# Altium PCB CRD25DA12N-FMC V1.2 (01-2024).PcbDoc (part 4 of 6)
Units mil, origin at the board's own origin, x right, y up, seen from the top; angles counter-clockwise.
Board outline 8000 x 8000 mil, 6 copper layers (Top Layer, Layer 2, Layer 3, Layer 4, Layer 5, Bottom Layer), stack 91 mil thick; 574 components, 325 nets, 1631 pads, 633 vias.
Unrouted connection lines stored in the file: 1.
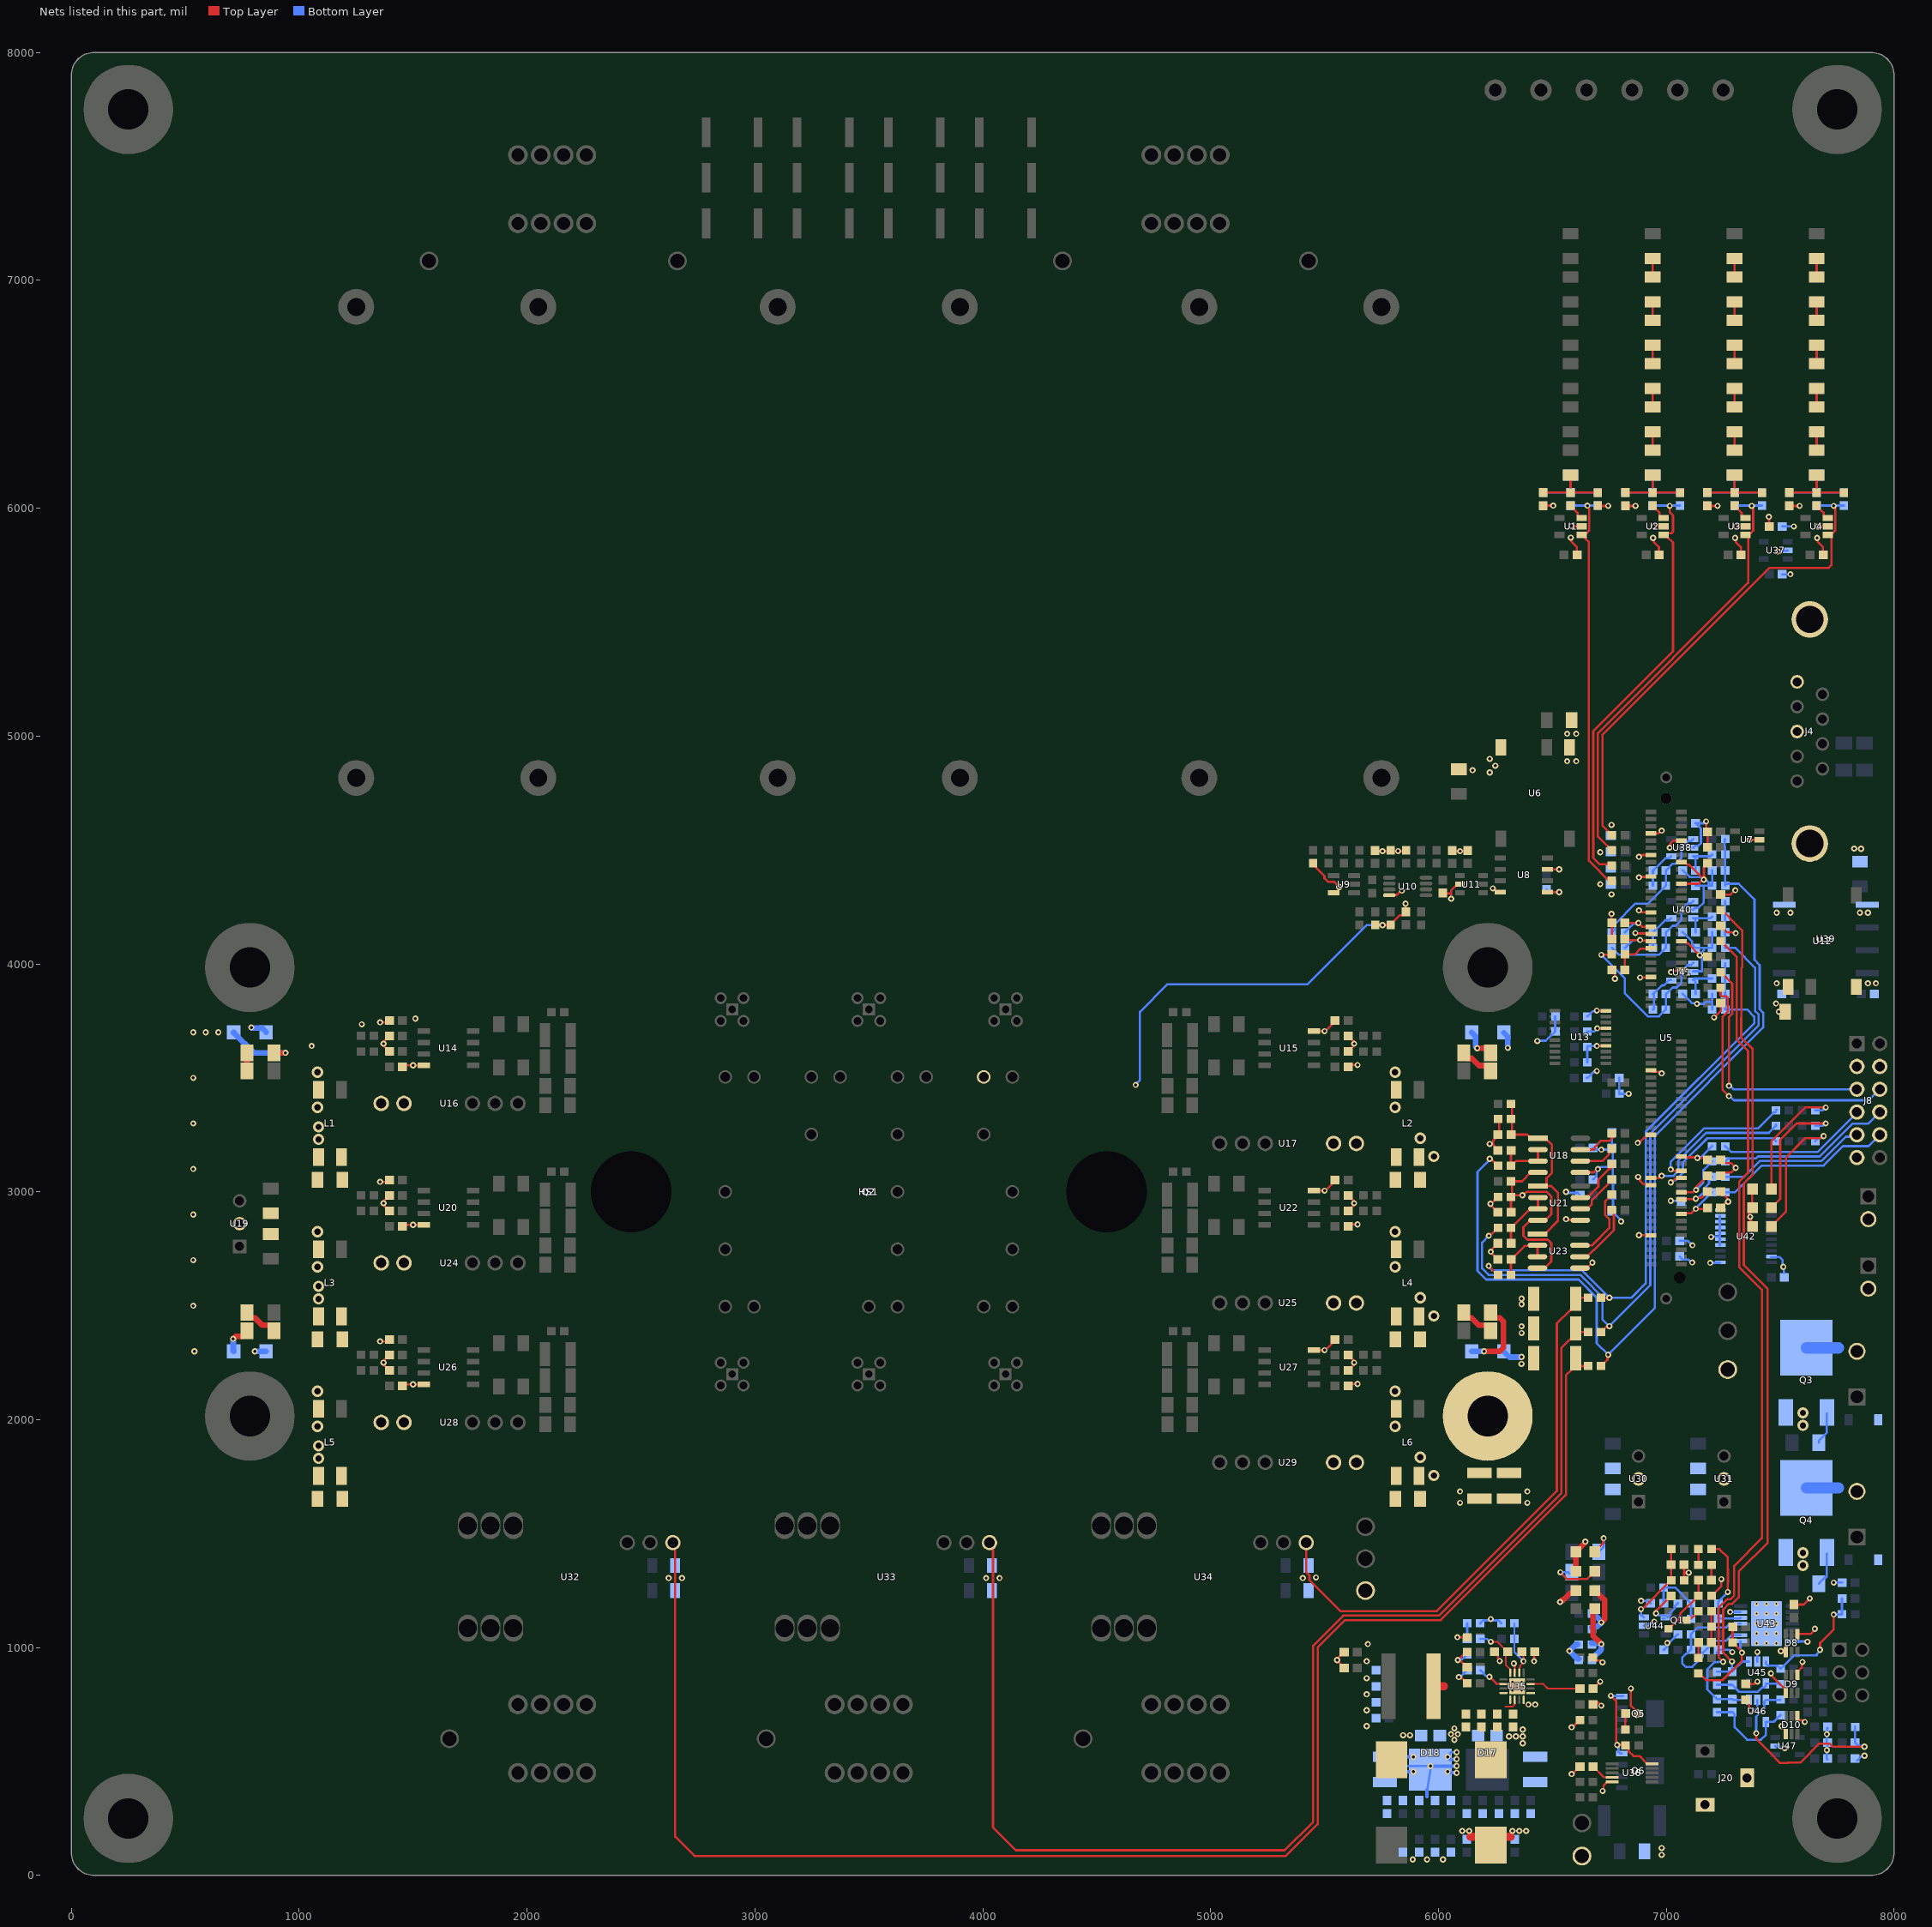
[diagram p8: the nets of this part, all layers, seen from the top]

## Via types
v1: diameter 27, hole 13, Top Layer to Bottom Layer, tented both sides, 537 vias
v2: diameter 50, hole 28, Top Layer to Bottom Layer, tented both sides, 76 vias
v3: diameter 19.68, hole 7.87, Top Layer to Bottom Layer, tented top, 15 vias
v4: diameter 19.68, hole 7.87, Top Layer to Bottom Layer, tented both sides, 5 vias

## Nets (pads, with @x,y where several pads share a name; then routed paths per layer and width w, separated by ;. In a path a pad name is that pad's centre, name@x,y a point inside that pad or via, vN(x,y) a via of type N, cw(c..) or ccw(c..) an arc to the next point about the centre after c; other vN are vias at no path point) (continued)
GND: C1.2 C2.2 C3.2 C4.2 C5.2 C6.2 C7.2 C8.2 C9.2 C10.2 C12.2 C13.2 C17.2 C19.2 C21.2 C22.2 C23.2 C24.2 C25.2 C26.2 C27.2 C28.2 C29.2 C32.2 C33.2 C34.2 C35.2 C38.2 C39.2 C44.2 C45.2 C46.2 C47.2 C50.2 C51.2 C54.2 C55.2 C56.2 C57.2 C58.2 C59.2 C60.2 C61.2 C64.2 C65.2 C66.2 C69.2 C70.2 C75.2 C76.2 C79.2 C80.2 C81.2 C82.2 C85.2 C86.2 C93.2 C96.2 C99.2 C100.2 C101.2 C102.2 C104.2 C105.2 C106.2 C107.2 C108.2 C113.2 C121.2 C122.2 C123.2 C124.2 C125.2 C127.2 C128.2 C129.2 C131.2 C132.2 C133.2 C134.2 C135.2 C137.2 C139.2 C140.2 C141.2 C143.2 C144.2 C145.2 C146.2 C147.2 C148.2 C149.2 C150.2 C151.2 C152.2 C153.2 C154.2 C155.2 C156.2 C157.2 C158.2 C159.2 C160.2 C161.2 C162.2 C163.2 C164.2 C165.2 C166.1 C167.1 C168.1 C170.2 C173.2 C174.2 C175.2 C176.2 C179.2 C182.2 C183.2 C184.2 C186.2 C187.2 C188.2 C190.2 C191.2 C192.2 C193.2 C194.2 C195.2 C196.2 C197.2 C198.2 C199.2 C200.2 C201.2 C202.2 C203.2 C204.2 C205.2 C206.2 C207.2 D1.1 D2.1 D3.1 D4.1 D5.1 D6.1 D8.1 D8.4 D9.1 D9.4 D10.1 D10.4 D11.1 D12.1 D13.1 D14.1 D18.1 J8.3 J8.4 J8.11 J9.2 J10.2 J20.2 J20.3 L1.2 L2.2 L3.2 L4.2 L5.2 L6.2 L9.1 Q3.3 Q4.3 R38.1 R83.1 R97.1 R105.1 R109.1 R117.1 R125.1 R126.1 R130.1 R131.1 R134.1 R137.1 R141.1 R142.1 R185.1 R190.1 R195.1 R197.1 R198.1 R199.1 R200.1 R201.1 R202.1 R203.1 R226.1 R229.1 R230.1 R231.1 R234.1 TP7.1 TP10.1 TP15.1 U1.2 U2.2 U3.2 U4.2 U5.7 U5.10 U5.13 U5.16 U5.19 U5.22 U5.29 U5.35 U5.38 U5.46 U5.47 U5.65 U5.83 U5.97 U5.111 U6.1 U7.2 U8.5 U8.7 U12.1 U13.4 U13.7 U13.10 U14.4 U15.4 U18.5 U19.2 U20.4 U21.5 U22.4 U23.5 U26.4 U27.4 U30.2 U31.2 U35.1 U35.7 U35.16 U35.17 U36.5 U37.2 U38.2 U39.4 U40.2 U41.2 U42.1 U42.4 U42.5 U42.6 U42.7 U42.8 U42.9 U42.10 U42.19 U43.6 U43.14 U43.15 U44.2 U45.2 U46.2 U47.2 | length 12249.7
  Top Layer w8: v1(6331.08,930) 6331.08,924.86 6335.16,920.78 6335.16,889.81 U35.7@6334.87,889.52 ; v1(6720.98,370.5) 6724.62,374.14 6724.62,394.48 U36.5@6739.86,409.72 ; U36.5@6740.77,410.63 U36.5@6762.91,410.63
  Top Layer w10: v1(1355,2343.5) 1382.92,2343.5 C75.2@1391.42,2352 ; v1(1355,3043.5) 1382.92,3043.5 C50.2@1391.42,3052 ; v1(1355,3743.5) 1382.92,3743.5 C28.2@1391.42,3752 ; C81.2@1391.42,2216 1391.42,2220.05 1373.25,2238.22 1373.25,2246.75 v1(1370,2250) 1373.25,2253.25 1373.25,2261.78 1391.42,2279.95 C79.2@1391.42,2284 ; C59.2@1391.42,2916 1391.42,2920.05 1373.25,2938.22 1373.25,2946.75 v1(1370,2950) 1373.25,2953.25 1373.25,2961.78 1391.42,2979.95 C56.2@1391.42,2984 ; C34.2@1391.42,3616 1391.42,3620.05 1373.25,3638.22 1373.25,3646.75 v1(1370,3650) 1373.25,3653.25 1373.25,3661.78 1391.42,3679.95 C32.2@1391.42,3684 ; C85.2@1448.58,2148 1455.58,2155 v1(1500,2155) U26.4@1546.73,2155 ; C64.2@1448.58,2848 1455.58,2855 v1(1500,2855) U20.4@1546.73,2855 ; C38.2@1448.58,3548 1455.58,3555 v1(1500,3555) U14.4@1546.73,3555 ; U27.4@5453.27,2305 v1(5500,2305) 5505,2305 5505,2306.53 5550.47,2352 C76.2@5551.42,2352 ; U22.4@5453.27,3005 v1(5500,3005) 5505,3005 5505,3006.53 5550.47,3052 C51.2@5551.42,3052 ; U15.4@5453.27,3705 v1(5500,3705) 5505,3705 5505,3706.53 5550.47,3752 C29.2@5551.42,3752 ; C102.2@5586.42,900 5586.42,912.05 5555,943.47 5555,949.53 5575.47,970 C99.2@5586.42,970 ; C86.2@5608.58,2148 5617.08,2156.5 v1(5645,2156.5) ; C82.2@5608.58,2216 5608.58,2220.05 5626.75,2238.22 5626.75,2246.75 v1(5630,2250) 5626.75,2253.25 5626.75,2261.78 5608.58,2279.95 C80.2@5608.58,2284 ; C65.2@5608.58,2848 5617.08,2856.5 v1(5645,2856.5) ; C60.2@5608.58,2916 5608.58,2920.05 5626.75,2938.22 5626.75,2946.75 v1(5630,2950) 5626.75,2953.25 5626.75,2961.78 5608.58,2979.95 C57.2@5608.58,2984 ; C39.2@5608.58,3548 5617.08,3556.5 v1(5645,3556.5) ; C35.2@5608.58,3616 5608.58,3620.05 5626.75,3638.22 5626.75,3646.75 v1(5630,3650) 5626.75,3653.25 5626.75,3661.78 5608.58,3679.95 C33.2@5608.58,3684 ; v1(6083.11,1045) R134.1@6126.38,1045 ; v1@6102.73,866.75 6125.47,844 R141.1@6126.38,844 ; v1(6135,195) 6135,175.86 6140.86,170 ; L9.1@6192.99,170 L9.1@6230,132.99 L9.1@6267.01,170 ; C100.2@6246.42,981 6247.37,981 6261.24,967.14 6261.24,952.5 6268.91,944.82 v1(6268.91,940.28) ; C70.2@6261.42,2703.96 6260.47,2703.96 6230,2734.43 v1(6230,2736.96) 6233.25,2740.21 6233.25,2746.74 6260.47,2773.96 C69.2@6261.42,2773.96 ; C61.2@6261.42,2909.96 6260.47,2909.96 6231.87,2938.55 6231.87,2943.57 v1(6228.62,2946.82) 6229.34,2946.82 6260.47,2977.96 R97.1@6261.38,2977.96 ; C61.2@6266.42,2909.96 C61.2@6266.38,2910 ; R83.1@6266.38,3319 6266.42,3318.96 6266.42,3251 6265.47,3251 6251.61,3237.14 6251.61,3236.19 6240.73,3225.3 6240.73,3206.75 6262.47,3185 C45.2@6275,3185 ; 6317.98,170 6323.84,175.86 6323.84,193.84 v1(6325,195) ; v1(6331.08,930) 6334.33,926.75 6334.33,921.07 v1@6334.87,920.53 ; v1(6420,940) 6420,977.42 C101.2@6423.58,981 ; C1.2@6460,6011.42 v1(6503.58,6011.42) ; U8.7@6478.35,4415 v1(6530,4415) ; U8.5@6485,4315 v1(6530,4315) ; v1(6560,2880) 6562.53,2877.47 6620.58,2877.47 U21.5@6623.06,2875 ; v1(6580.67,5871.13) 6583.92,5867.88 6583.92,5853.71 6607.63,5830 6607.63,5795.95 C6.2@6608.58,5795 ; v1(6583.58,5921.42) 6584.29,5920.71 6627.52,5920.71 U1.2@6628.23,5920 ; v1(6585,445) 6587.47,445 6620.47,478 C113.2@6621.42,478 ; v1(6585,650) 6588.47,650 6618.47,680 R142.1@6625,680 ; U23.5@6621.11,2665 6652.04,2665 6675.82,2688.78 v1(6675.82,2689.09) ; U18.5@6623.06,3085 6623.41,3085.36 6680.76,3085.36 6695.4,3100 v1(6700,3100) ; C107.2@6678.58,750 6685.82,757.24 6700.74,757.24 ; C105.2@6678.58,819 6679.53,819 6710,849.47 v1(6710,850) ; R137.1@6678.62,956 6691.58,943.04 6707.36,943.04 6715.4,935 v1(6720,935) ; v1(6695,3640) 6695.3,3640.3 6734.7,3640.3 U13.4@6735,3640.59 ; v1(6695,3795) 6695.43,3794.57 6734.57,3794.57 U13.10@6735,3794.13 ; v1(6697.19,3717.36) U13.7@6735,3717.36 ; R38.1@6700,6011.38 6701.38,6010 v1(6745,6010) ; 6701.75,758.25 v1(6715,745) ; U36.5@6739.86,409.72 U36.5@6740.77,410.63 ; v1(6760,4220) 6760,4181.42 C21.2@6761.42,4180 C23.2@6761.42,4110 ; C25.2@6761.42,3974 6775,3960.42 v1(6775,3935) ; C2.2@6820,6011.42 6821.42,6010 v1(6865,6010) ; v1(6845,820) 6845,743.58 6863.76,724.81 6863.76,723.86 6877.63,710 C108.2@6878.58,710 ; v1(6864.55,4135.68) 6866.54,4133.69 6931.08,4133.69 U5.35@6933.07,4131.69 ; v1(6875,3215) 6878.25,3218.25 6884,3218.25 6904.89,3239.15 6908.64,3239.15 6919.29,3249.8 U5.83@6933.07,3249.8 ; v1(6876.5,3065) 6876.5,3060.4 6884.75,3052.15 6884.75,3048.22 6898.8,3034.17 6928.23,3034.17 U5.97@6933.07,3029.33 ; v1(6880,2810) 6880.57,2809.43 6929.43,2809.43 U5.111@6930,2810 ; v1(6880,4235) 6884.6,4235 6893.42,4226.18 U5.29@6933.07,4226.18 ; v1(6880,4380) 6881.83,4381.83 6931.24,4381.83 U5.19@6933.07,4383.66 ; v1(6880,4470) 6884.6,4470 6892.75,4478.15 U5.13@6933.07,4478.15 ; v1(6885,3940) 6885.47,3940.47 6934.53,3940.47 U5.47@6935,3940.94 ; U5.7@6933.07,4572.64 6966.29,4572.64 6978.65,4585 v1(6980,4585) ; U5.65@6935,3531.5 6939.84,3526.65 6968.75,3526.65 6975.4,3520 v1(6980,3520) ; v1(6942.09,5869.71) 6945.34,5866.45 6945.34,5852.28 6967.63,5830 6967.63,5795.95 C7.2@6968.58,5795 ; v1(6945,5920) U2.2@6988.23,5920 ; v1(7015,4510) 7018.25,4513.25 7018.25,4528.25 7031.14,4541.14 U5.10@7066.93,4541.14 ; v1(7021.31,3964.12) 7025.91,3964.12 7031.16,3969.37 7063.35,3969.37 U5.46@7067.64,3973.66 ; U5.38@7066.93,4100.2 7080.71,4100.2 7091.36,4089.54 7095.45,4089.54 v1(7147.18,4037.82) 7175.61,4037.82 C24.2@7181.42,4032 ; U5.22@7066.93,4352.17 7142.57,4352.17 7160.4,4370 v1(7165,4370) ; U5.16@7071.77,4451.5 U5.16@7066.93,4446.65 7080.71,4446.65 7091.36,4436 7099,4436 v1(7165,4370) ; R130.1@7078.62,1295 R130.1@7078.62,1295 7078.58,1330 ; C93.2@7078.58,1363 7078.58,1330 ; C93.2@7079.53,1347.25 C93.2@7079.53,1363 ; v1(7098.39,1328.39) 7080.19,1328.39 cw(c7080.19,1330) 7078.58,1330 ; v1(7175,4625) 7175,4586.42 C12.2@7181.42,4580 C13.2@7181.42,4511 ; C3.2@7180,6011.42 7181.42,6010 v1(7225,6010) ; C17.2@7181.42,4442 7180.47,4442 7166.61,4428.14 7166.61,4427.19 7165,4425.58 v1(7165,4370) ; R131.1@7198.62,1227 7199.53,1227 7241.89,1269.36 v1(7241.89,1300) ; v1(7210,3765) 7240,3795 7240,3826.58 C26.2@7238.58,3828 ; C58.2@7238.58,2930 7239.53,2930 7262.82,2953.29 7268.25,2953.29 v1(7271.5,2956.54) 7268.25,2959.8 7268.25,2971.28 7239.53,3000 C55.2@7238.58,3000 ; C47.2@7238.58,3070 7235,3070 7230,3075 7238.86,3083.86 7283.86,3083.86 v1(7305,3105) 7283.86,3126.14 7252.44,3126.14 C46.2@7238.58,3140 ; C22.2@7238.58,4168 7239.53,4168 7269.27,4138.25 7301.75,4138.25 v1(7305,4135) ; C19.2@7238.58,4304 7281.99,4304 7301.26,4323.27 v1(7303.03,4323.27) ; v1(7302.09,5869.71) 7305.34,5866.45 7305.34,5852.28 7327.63,5830 7327.63,5795.95 C8.2@7328.58,5795 ; v1(7305,5920) U3.2@7348.23,5920 ; C106.2@7348.58,771 7349.53,771 7363.39,757.14 7363.39,735.07 7370,728.46 v1(7370,723.86) ; C104.2@7348.58,840 7385.52,840 7395.52,850 v1(7400.12,850) ; v1@7360.04,2893.32 7360,2893.28 7360,2885 v1@7361.75,2883.25 ; v1(7365,4545) U7.2@7408.15,4545 ; D2.1@7365.51,2949.17 7367.17,2949.17 D2.1@7367.17,2950.83 ; D2.1@7372.7,2911.63 7361.51,2911.63 7361.26,2911.38 7361.26,2897.24 v1(7368.5,2890) v1@7361.75,2883.25 ; D3.1@7375,2870 v1@7361.75,2883.25 ; D2.1@7375,2948.66 7376.34,2950 D1.1@7376.34,3029.21 ; v1(7450,5962.36) 7451.14,5961.23 C5.2@7451.14,5920 ; v1(7459.15,886.52) 7462.41,883.26 7462.41,876.41 7524.41,814.41 D9.1@7524.41,800.63 ; v1(7502.68,984.44) 7520.6,984.44 D8.1@7524.41,980.63 ; v1(7506,655.26) 7506,652.82 7520.55,638.27 D10.1@7520.55,625 ; C4.2@7540,6011.42 7541.42,6010 v1(7585,6010) ; C96.2@7560,1188.58 7603.58,1188.58 v1(7630,1215) ; D10.4@7575.59,699.37 7575.59,685.59 7579.45,681.73 7594.67,681.73 7603.29,673.11 v1(7607.89,673.11) ; D9.4@7575.59,879.37 7575.59,893.15 7594.61,912.17 7594.61,933.41 v1(7597.86,936.66) ; D8.4@7575.59,1059.37 7633.25,1059.37 7652.35,1078.46 v1(7652.35,1082.35) ; v1(7662.09,5869.71) 7665.34,5866.45 7665.34,5852.28 7687.63,5830 7687.63,5795.95 C9.2@7688.58,5795 ; v1(7665,5920) U4.2@7708.23,5920
  Top Layer w25: v1(6534.01,1199.85) 6534.55,1199.85 6542,1207.3 6547.3,1207.3 6578.88,1238.88 6592.54,1238.88 D6.1@6603.66,1250 ; D5.1@6603.66,1335 D4.1@6603.66,1420 6644.62,1460.96 6644.62,1464.62 v1(6645,1465)
  Top Layer w35: 6140.86,170 L9.1@6192.99,170 ; L9.1@6267.01,170 6317.98,170
  Bottom Layer w10: 5860,480 v1(5965,480) ; D18.1@5950,376.14 D18.1@5965,464.06 ; v1(6040,455) D18.1@6045,450 ; D18.1@6050,510 v1(6040,520) 6040,525.51 6054.49,540 v1(6080,540) ; v1(6090,870) 6093.25,873.25 6098.73,873.25 6125.47,900 C175.2@6126.42,900 ; R226.1@6183.62,1106 6196.58,1118.96 6219.36,1118.96 6225.4,1125 6234.6,1125 6240.64,1118.96 6263.42,1118.96 R230.1@6276.38,1106 ; D13.1@6287.4,2298.03 D13.1@6287.4,2300 ; D11.1@6287.4,3698.03 D11.1@6287.4,3700 ; D13.1@6311.93,2273.5 D13.1@6313.9,2273.5 ; v1(6433.85,3661.83) 6434.99,3662.97 6471.31,3662.97 6511.34,3703 6512.24,3703 R198.1@6512.24,3770 ; C131.2@6475,4326.42 6486.42,4315 v1(6530,4315) ; v1(6560,3000) 6564.6,3000 6569.6,2995 6611.42,2995 C153.2@6621.42,2985 ; C144.2@6650,3500 C144.2@6653.58,3500 6654.53,3500 6681.27,3526.75 6691.75,3526.75 v1(6695,3530) ; R202.1@6653.62,3568 R201.1@6653.62,3636 6657.62,3640 v1(6695,3640) ; R199.1@6653.62,3703 6682.82,3703 v1(6697.19,3717.36) ; R197.1@6653.62,3770 6654.53,3770 6676.27,3791.75 6691.75,3791.75 v1(6695,3795) ; C150.2@6678.58,3054 6679.53,3054 6693.39,3067.86 6693.39,3088.79 6700,3095.4 v1(6700,3100) 6704.6,3100 6713.74,3109.14 6747.56,3109.14 C148.2@6761.42,3123 ; C147.2@6678.58,3192 6685.58,3185 v1(6715,3185) 6756.46,3185 C146.2@6761.46,3180 ; 6761.46,3240 C146.2@6761.46,3180 ; C143.2@6793.58,3500 R203.1@6793.62,3430 R203.1@6793.62,3430 v1(6835,3430) ; v1(6801.5,2870) 6798.25,2873.25 6798.25,2879.13 6756.07,2921.3 6752.76,2921.3 6766.46,2935 6766.46,3055.63 6765,3057.09 6765,3176.46 C146.2@6761.46,3180 ; v1(6889.85,1205.15) 6920.27,1205.15 C170.2@6931.42,1194 ; U44.2@6901.77,1095 6910.55,1103.78 6932.8,1103.78 6942.81,1113.79 v1(6947.41,1113.79) ; C174.2@6988.58,990 6989.53,990 7003.39,1003.86 7003.39,1012.47 7007.99,1017.07 v1@7009.28,1017.07 ; v1(7005.01,1020.32) 7006.03,1020.32 v1@7009.28,1017.07 ; v1(7019.81,2960) 7062.85,2960 C151.2@7065,2957.85 ; R229.1@7050.47,1058 7031.87,1039.39 7031.87,1039.26 7012.92,1020.32 7012.53,1020.32 v1@7009.28,1017.07 ; C156.2@7058.58,2716 7072.44,2702.14 7097.31,2702.14 7109.45,2690 v1(7114.05,2690) ; C155.2@7058.58,2785 7094.69,2785 7114.69,2765 v1(7115,2765) ; C141.2@7071.42,3868 7072.37,3868 7112.12,3828.25 7131.75,3828.25 v1(7135,3825) 7166,3825 7175.02,3834.02 7201.42,3834.02 ; C135.2@7071.42,4139 7072.37,4139 7113.76,4097.61 7113.76,4083.86 7127.63,4070 C137.2@7128.58,4070 7164.98,4070 ; C129.2@7071.42,4411 7072.37,4411 7102.24,4381.14 7150.33,4381.14 7161.47,4370 v1(7165,4370) 7168.25,4366.75 7176.73,4366.75 R185.1@7200.47,4343 ; U41.2@7118.23,3967 7119.23,3968.01 7156.78,3968.01 7156.78,4023.62 7147.18,4033.22 v1(7147.18,4037.82) 7147.18,4042.42 7164.98,4060.21 7164.98,4070 ; U40.2@7118.23,4238 7127.01,4246.78 7141.58,4246.78 7164.52,4269.72 7164.52,4343 ; U38.2@7118.23,4510 7127.01,4518.78 7141.58,4518.78 7151.87,4529.07 7151.87,4594.66 C123.2@7129.53,4617 ; C133.2@7128.58,4343 7164.52,4343 ; C123.2@7128.58,4617 C123.2@7129.53,4617 ; v1(7175,4625) 7170.4,4625 7162.4,4617 C123.2@7129.53,4617 ; v1(7193.1,2688.1) 7193.46,2688.46 7234.64,2688.46 U42.1@7235,2688.82 ; v1(7196.63,2801.63) 7198.98,2803.98 7235,2803.98 ; R195.1@7201.38,3800 R195.1@7201.38,3800 7201.42,3834.02 ; C140.2@7201.42,3868 7201.42,3834.02 ; C134.2@7201.42,4139 C134.2@7201.42,4139 R190.1@7201.38,4070 7164.98,4070 ; C128.2@7201.42,4411 C128.2@7201.42,4411 R185.1@7201.38,4343 R185.1@7200.47,4343 ; C173.2@7220.28,975.24 C173.2@7230.05,985 ; C173.2@7228.58,990 7275.4,990 7285.4,980 v1(7290,980) ; U42.4@7235,2765.59 7235,2803.98 ; U42.9@7235,2893.54 7235,2803.98 ; U42.10@7235,2919.13 7246.97,2919.13 7249.85,2922.01 7249.85,2939.85 7252.01,2942.01 7252.36,2942.01 7266.9,2956.54 v1(7271.5,2956.54) ; v1(7280.29,1156.3) 7280.35,1156.24 U43.6@7325.83,1156.18 U43.6@7325.83,1156.18 ; v1(7370,723.86) 7373.25,727.11 7389.98,727.11 7400,737.14 U46.2@7400,770 ; U45.2@7400,938.23 v1(7400,980) ; U42.19@7459.41,2714.41 7495.59,2714.41 7510.88,2699.12 7510.88,2673.19 v1(7513.45,2670.62) 7516.7,2667.37 7516.7,2646.84 7518.54,2645 ; U47.2@7478.7,567.6 7485.51,560.79 7509.61,560.79 7509.77,560.62 7517.87,560.62 v1(7520,558.49) ; v1(7490,5810) 7492.5,5812.5 7530.65,5812.5 U37.2@7533.15,5815 ; C122.2@7508.58,5710 v1(7545,5710) ; C121.2@7508.58,5920 v1(7560,5920) ; U43.14@7554.17,1028.23 7555.63,1026.77 7618.55,1026.77 v1(7620,1025.32) ; v1(7705,550) 7705,511.58 C188.2@7708.58,508 ; v1(7705,620) 7705,581.58 7708.58,578 v1@7708.58,550 ; v1@7706.69,620 7706.69,645.11 C184.2@7708.58,647 ; v1(7735,1285) C165.2@7771.42,1285 ; C187.2@7838.53,504 7856.27,521.75 7866.75,521.75 v1(7870,525) ; 7164.52,4343 R185.1@7200.47,4343
  Bottom Layer w15: 5855,520 v1(5890,520) ; 5860,455 v1(5890,455) ; 5950,345 D18.1@5950,376.14 ; v1(5965,480) v1(6080,480) ; D18.1@6045,450 v1(6080,450) ; D18.1@6050,510 v1(6080,510)
  Bottom Layer w25: v1(790,3721.08) 790.54,3721.08 792.62,3719 837.3,3719 854.33,3701.97 D12.1@854.33,3700 ; v1(805,2300) D14.1@854.33,2300 ; D13.1@6287.4,2298.03 D13.1@6311.93,2273.5 ; D11.1@6287.4,3698.03 6304.43,3681 6304.43,3632.61 6305,3632.04 v1(6305,3631.5) ; D13.1@6313.9,2273.5 6315.01,2274.62 6364.62,2274.62 v1(6365,2275) ; R231.1@6610,1013.53 6603.53,1013.53 v1(6575,985) 6575.47,985 6610.47,950 R234.1@6616.47,950
  other v1: 5887.4,70 5950,70 6020,70 6980,90 6980,120 6105,195 6355,195 6385,195 5685,655 5685,725 6395,750 6425,750 5685,795 5685,865 5685,940 5555,945 5690,1014.94 6230,1125 2621.5,1305 2680,1305 4015,1305 4073.5,1305 5405,1305 5462.65,1307.65 6095,1635 6390,1635 6095,1685 6390,1685 6364.7,2244.7 540,2300 6365,2380 6364.85,2409.85 535,2500 6365,2506.5 6365,2531.5 535,2700 535,2900 535,3100 6225,3210 535,3300 535,3500 1055,3640 535,3700 590,3700 645,3700 1275,3735 1510,3760 7494.21,3790 7481.72,3826.72 7485,3915 7485,4225 7545,4225 6760,4305 6710,4350 6710,4490 6760,4610 6565,4890 6605,4890 6565,5010 6605,5010
  other v2: 7600,1360 7600,1415 1080,1970 5810,1970 7600,1974.76 7600,2029.76 1080,2125 5810,2125 1080,2670 5810,2670 1080,2825 5810,2825 1080,3370 5810,3370 1080,3525 5810,3525
  other v3: 7396.69,1018.39 7440,1018.39 7483.31,1018.39 7396.69,1061.69 7440,1061.69 7483.31,1061.69 7396.69,1105 7440,1105 7483.31,1105 7396.69,1148.31 7440,1148.31 7483.31,1148.31 7396.69,1191.61 7440,1191.61 7483.31,1191.61
  other v4: 6325,810 6365,810 6345,830 6325,850 6365,850
GND_ISO: C126.2 C138.2 J4.3 J4.5 J4.10 J4.11 U12.4 U39.5
  other v1: 7885,3915 7920,3915 7850,4225 7885,4225 7855,4505 7824.6,4506.19
GND_NTC: C11.2 C14.2 C15.2 C16.2 C18.2 C20.2 Q2.NTC1 R46.1 R51.1 R52.1 R60.1 R61.1 U6.4 U8.4 U9.5 U10.4 U11.2 | length 2383.2
  Top Layer w10: R46.1@5450,4436.38 5450,4435.47 5500,4385.47 5500,4375.87 5515.87,4360 5543.1,4360 v1(5565,4338.1) 5565,4333.5 5560.91,4329.41 5560.91,4319.21 5554.29,4312.6 U9.5@5539.92,4312.6 ; R60.1@5722,4171.38 5723.38,4170 v1(5755,4170) 5788.62,4170 R61.1@5790,4171.38 5790,4172.28 5831.48,4213.76 5844.14,4213.76 5858,4227.63 C20.2@5858,4228.58 5855.78,4230.8 v1(5855.78,4264.61) ; C14.2@5722,4493.58 5723.42,4495 v1(5755,4495) 5788.62,4495 5790,4493.62 R52.1@5858,4493.62 ; U10.4@5784.29,4301.61 5785.77,4303.09 5817.82,4303.09 5836.04,4321.31 v1(5839.9,4321.31) ; C18.2@6020,4311.42 6021.42,4310 6055,4310 ; v1@6055,4290 6055.64,4290.64 6055.64,4321.66 6083.98,4350 U11.2@6093.82,4350 ; C15.2@6060,4493.58 6061.42,4495 v1(6095,4495) 6126.58,4495 C16.2@6128,4493.58 ; v1(6238.99,4331.3) 6241.57,4331.3 6257.87,4315 U8.4@6271.65,4315
  Bottom Layer w10: v1(4671.61,3468.79) 4671.61,3472.32 4690,3490.71 4690,3790 4810,3910 5425,3910 5685,4170 v1(5755,4170)
  other v1: 6055.64,4286.1 5823,4495.04 6225,4840 6150,4850 6250,4870 6225,4900
GPIO35: C46.1 R210.2 U5.90 | length 202.3
  Top Layer w10: U5.90@7066.93,3155.31 7070.74,3151.5 v1@7133.49,3151.51 ; v1(7136.75,3148.25) 7173.17,3148.25 C46.1@7181.42,3140
  Bottom Layer w10: v1(7136.75,3148.25) 7140,3151.51 7151.98,3151.51 7200.47,3200 R210.2@7201.38,3200
GPIO54: C47.1 R211.2 U5.100 | length 306
  Top Layer w10: U5.100@7066.93,2997.83 7115.93,2997.83 7126.35,3008.25 v1(7130.95,3008.25) 7133.25,3010.55 7133.25,3022.78 7180.47,3070 C47.1@7181.42,3070
  Bottom Layer w10: v1(7130.95,3008.25) 7162.55,3039.83 7162.55,3095.08 7200.47,3133 R211.2@7201.38,3133
GPIO55: C55.1 R212.2 U5.102 | length 257.6
  Top Layer w10: U5.102@7066.93,2966.34 7068.76,2968.17 7128.17,2968.17 v1(7130,2970) 7133.25,2973.25 7153.73,2973.25 7180.47,3000 C55.1@7181.42,3000
  Bottom Layer w10: v1(7130,2970) 7133.25,2973.25 7138.56,2973.25 7164.66,2999.36 7164.66,3013.66 7187.52,3036.51 7187.52,3053.04 7200.47,3066 R212.2@7201.38,3066
GPIO57: C58.1 R213.2 U5.106 | length 229.4
  Top Layer w10: U5.106@7066.93,2903.35 7068.73,2905.15 7109.54,2905.15 7129.39,2925 v1(7130,2925) 7176.42,2925 ccw(c7176.42,2930) C58.1@7181.42,2930
  Bottom Layer w10: v1(7130,2925) 7130,2927.53 7200.47,2998 R213.2@7201.38,2998
HI_OC_REF: C44.1 R82.1 R83.2 U18.1 U21.1 U23.1 | length 857.2
  Top Layer w10: R82.1@6323.62,3386 6323.62,3319 6323.62,3251.04 6323.58,3251 6389.7,3251 6405.7,3235 U18.1@6436.94,3235 6468.19,3235 6498.19,3205 6498.19,3083.24 6474.64,3059.7 6474.64,3031.46 U21.1@6468.19,3025 ; U23.1@6435,2815 6466.24,2815 6525,2873.76 6525,2995 6495,3025 U21.1@6468.19,3025 ; U21.1@6436.94,3025 U21.1@6468.19,3025
IU: R117.2 R120.1 U32.9 | length 7014.5
  Top Layer w10: U32.9@2640,1460 2650,1450 2650,170 2735,85 5330,85 5470,225 5470,1000 5590,1120 6010,1120 6560,1670 6560,2195 6582.91,2217.91 6582.91,2235.39 R117.2@6602.52,2255 ; R117.2@6602.52,2254.61 6622.13,2235 R120.1@6656.38,2235
IU_FILT: C128.1 R87.1 R120.2 R183.1 R184.1 R185.2 | length 4130.5
  Top Layer w10: v1(6225,3145) 6229.47,3145 6260.47,3114 R87.1@6261.38,3114 ; R120.2@6713.62,2235 6714.53,2235 6741.75,2262.22 6741.75,2281.75 v1(6745,2285)
  Bottom Layer w10: v1(6225,3145) 6225,3140.4 6213.54,3128.94 6213.54,3128.54 6171.5,3086.5 6171.5,2653.5 6210,2615 6615,2615 6695,2535 6695,2335 v1(6745,2285) 6950,2490 6950,3245.31 7425.71,3721.02 7425.71,3785.85 7410,3801.57 7410,3995 7387,4018 7387,4283 7318.23,4351.77 7260.39,4351.77 R185.2@7258.62,4350 ; R185.2@7258.62,4343 R185.2@7258.62,4350 ; R183.1@7258.62,4548 7255.96,4545.33 7255.96,4515.04 7258.62,4512.38 R184.1@7258.62,4480 R184.1@7258.62,4480 C128.1@7258.58,4411 C128.1@7258.58,4411 R185.2@7258.62,4350
IU_MEAS: C21.1 R189.2 U5.33 | length 197.7
  Top Layer w10: C21.1@6818.58,4180 v1(6877.48,4180) 6894.45,4163.03 U5.33@6933.39,4163.03
  Bottom Layer w10: R189.2@6818.62,4139 6819.53,4139 6857.27,4176.75 6874.22,4176.75 v1(6877.48,4180)
IV: R109.2 R114.1 U33.9 | length 5685.2
  Top Layer w10: U33.9@4030,1460 4030,1444.51 4045,1429.51 4045,210 4145,110 5325,110 5450,235 5450,1008.28 5581.72,1140 5675,1140 6001.72,1140 6540,1678.28 6540,2315 6576.85,2351.85 6582.91,2351.85 6602.52,2371.46 6602.52,2385 R114.1@6656.38,2385
IV_FILT: C134.1 R103.1 R114.2 R187.1 R188.1 R190.2 | length 3215
  Top Layer w10: v1(6220.91,2806.96) 6224.16,2810.21 6229.63,2810.21 R103.1@6261.38,2841.96 R103.1@6262.28,2841.96 ; R114.2@6713.62,2385 6714.53,2385 6736.27,2406.75 6746.75,2406.75 v1(6750,2410)
  Bottom Layer w10: v1@6229.13,2815.18 v1(6220.91,2806.96) 6191.5,2777.55 6191.5,2663.5 6220,2635 6623.28,2635 6638.28,2620 6720,2538.28 6720,2440 v1(6750,2410) 6930,2590 6930,3255 7405.71,3730.71 7405.71,3777.57 7390,3793.28 7390,3983.81 7303.81,4070 R190.2@7258.62,4070 C134.1@7258.58,4139 C134.1@7258.58,4139 C134.1@7258.58,4139 R188.1@7258.62,4207 R187.1@7258.62,4275
IV_MEAS: C23.1 R192.2 U5.37 | length 208.3
  Top Layer w10: C23.1@6809.06,4104.85 v1(6885,4104.85) 6887.32,4102.52 6930.9,4102.52 U5.37@6934.21,4099.21
  Bottom Layer w10: R192.2@6818.62,4070 6819.53,4070 6854.37,4104.85 v1(6885,4104.85)
IW: R105.2 R106.1 U34.9 | length 2439.7
  Top Layer w10: U34.9@5420,1460 5420,1330.31 5434.15,1316.15 5434.15,1295.85 5570,1160 5993.43,1160 6520,1686.57 6520,2422.48 6579.37,2481.85 6584.37,2481.85 R105.2@6607.52,2505 ; R105.2@6607.52,2535 R106.1@6659.41,2535
IW_FILT: C140.1 R104.1 R106.2 R193.1 R194.1 R195.2 | length 2582.4
  Top Layer w10: v1(6220.46,2674.84) 6220.59,2674.84 6260.47,2634.96 R104.1@6261.38,2634.96 ; R106.2@6713.62,2535 v1(6750,2535)
  Bottom Layer w10: v1(6220.46,2674.84) 6220.46,2670.24 6235,2655.7 6235,2655 6631.57,2655 6646.57,2640 6750,2536.57 v1(6750,2535) 6846.72,2535 6910,2598.28 6910,3263.28 7385.71,3739 7385.71,3769.29 7355,3800 R195.2@7258.62,3800 R195.2@7258.62,3800 C140.1@7258.58,3868 R194.1@7258.62,3936 R194.1@7258.62,3936 R193.1@7258.62,4003
IW_MEAS: C25.1 R64.2 U5.39 | length 194.9
  Top Layer w10: C25.1@6818.58,3974 R64.2@6818.62,4042 R64.2@6818.62,4042 6861.55,4042 6886.48,4066.93 6935,4066.93 U5.39@6934.85,4066.78
LED_G: R209.2 U5.96 | length 628.7
  Top Layer w10: v1(7019.92,3041.5) 7024.52,3041.5 7039.01,3055.98 7062.09,3055.98 U5.96@7066.93,3060.83
  Bottom Layer w10: v1(7019.92,3041.5) 7024.52,3041.5 7033.02,3050 7040.09,3050 7073.19,3083.1 7073.19,3128.49 7179.69,3235 7410,3235 7410.04,3234.96 7455.04,3234.96 ; 7455,3235 7455.04,3234.96 ; R209.2@7481.38,3222 7468.42,3234.96 7455.04,3234.96
LED_R: R205.2 U5.94 | length 637.2
  Top Layer w10: v1(7020,3098.5) 7024.6,3098.5 7030.78,3092.32 U5.94@7066.93,3092.32
  Bottom Layer w10: v1(7020,3098.5) 7020,3131.87 7166.56,3278.44 7403.44,3278.44 7467.52,3342.52 7467.52,3345.04 7472.47,3350 R205.2@7480,3350 ; R205.2@7482.47,3360 R205.2@7485,3360
LED_Y: R207.2 U5.95 | length 674.3
  Top Layer w10: U5.95@6933.07,3060.83 6933.48,3060.41 6966.29,3060.41 6975.88,3070 v1(6980,3070)
  Bottom Layer w10: v1(6980,3070) 7031.81,3070 7053.19,3091.38 7053.19,3136.77 7174.85,3258.44 7450,3258.44 ; 7450,3260 7450.47,3260 7480,3289.53 R207.2@7480,3295 ; R207.2@7480.47,3290 R207.2@7481.38,3290
LO_OC_REF: C61.1 R91.1 R97.2 U18.4 U21.4 U23.4 | length 1027.5
  Top Layer w10: C61.1@6318.58,2909.96 6318.58,2973 R97.2@6323.58,2978 ; R91.1@6318.62,3045.96 R91.1@6323.58,3045.96 ; U23.4@6403.62,2665 U23.4@6435,2665 6466.24,2665 6495,2693.76 6495,2775 6480,2790 6390,2790 6372.85,2807.15 6372.85,2845 6402.85,2875 U21.4@6436.94,2875 6468.19,2875 6495,2901.81 6495,2980 6475,3000 6388.36,3000 6373.22,2984.86 v1(6368.62,2984.86) 6330.44,2984.86 R97.2@6323.58,2978 ; U18.4@6421.32,3085 6405.7,3085 6366.66,3045.96 R91.1@6323.58,3045.96 ; R97.2@6323.58,2978 R91.1@6323.58,3045.96
NetC1_1: C1.1 R33.2 R37.1 R38.2 | length 316.3
  Top Layer w10: C1.1@6460,6068.58 R37.1@6580,6068.62 R37.1@6580,6068.62 ; R33.2@6580,6144.88 R37.1@6580,6068.62 ; R38.2@6700,6068.62 R37.1@6580,6068.62
NetC2_1: C2.1 R34.2 R39.1 R40.1 | length 316.3
  Top Layer w10: C2.1@6820,6068.58 R39.1@6940,6068.62 R39.1@6940,6068.62 ; R34.2@6940,6144.88 R39.1@6940,6068.62 ; R40.1@7060,6068.62 R39.1@6940,6068.62
NetC3_1: C3.1 R35.2 R41.1 R42.1 | length 316.3
  Top Layer w10: C3.1@7180,6068.58 R41.1@7300,6068.62 R41.1@7300,6068.62 ; R35.2@7300,6144.88 R41.1@7300,6068.62 ; R42.1@7420,6068.62 R41.1@7300,6068.62
NetC4_1: C4.1 R36.2 R43.1 R44.1 | length 316.3
  Top Layer w10: C4.1@7540,6068.58 C4.1@7540,6068.58 R43.1@7660,6068.62 ; R36.2@7660,6144.88 R43.1@7660,6068.62 ; R44.1@7780,6068.62 R43.1@7660,6068.62
NetC45_1: C45.1 R87.2 U18.2 U18.3 | length 245.6
  Top Layer w10: C45.1@6318.58,3182 C45.1@6318.58,3182 R87.2@6318.62,3114 6319.53,3114 6340.53,3135 U18.3@6436.94,3135 U18.2@6436.94,3185 U18.2@6436.82,3184.87 ; C45.1@6324.21,3185 C45.1@6324.47,3184.74
NetC48_1: C48.1 L1.4 U16.1
NetC48_2: C48.2 L1.3 U16.2
  other v2: 1085,3230 1085,3285
NetC49_1: C49.1 L2.4 U17.1
  other v2: 5980,3155 5920,3235
NetC49_2: C49.2 L2.3 U17.2
NetC69_1: C69.1 R103.2 U21.2 U21.3 | length 270.2
  Top Layer w10: C69.1@6318.58,2773.96 6318.58,2841 6402.57,2925 U21.3@6436.94,2925 U21.2@6436.94,2975
NetC70_1: C70.1 R104.2 U23.2 U23.3 | length 259.9
  Top Layer w10: R104.2@6318.62,2634.96 R104.2@6318.62,2634.96 6318.58,2703.04 C70.1@6318.62,2703 ; C70.1@6318.58,2703.96 6319.53,2703.96 6378.1,2762.53 6432.53,2762.53 U23.2@6435,2765 U23.3@6435,2715
NetC73_1: C73.1 L3.4 U24.1
NetC73_2: C73.2 L3.3 U24.2 | length 4.1
  Top Layer w10: L3.3@1090,2452.36 L3.3@1092.89,2455.26
  other v2: 1085,2530 1085,2585
NetC74_1: C74.1 L4.4 U25.1
  other v2: 5980,2455 5920,2535
NetC74_2: C74.2 L4.3 U25.2
NetC91_1: C91.1 L5.4 U28.1
NetC91_2: C91.2 L5.3 U28.2
  other v2: 1085,1830 1085,1885
NetC92_1: C92.1 L6.4 U29.1
  other v2: 5980,1755 5920,1835
NetC92_2: C92.2 L6.3 U29.2
NetC93_1: C93.1 R127.1 R130.2 U44.3 | length 364.9
  Top Layer w10: v1(6889.16,1168.01) 6893.48,1168.01 7020.47,1295 R130.2@7021.38,1295 C93.1@7021.42,1363 C93.1@7021.42,1363 R127.1@7021.38,1432 R127.1@7021.38,1432
  Bottom Layer w10: v1(6889.16,1168.01) 6889.16,1141.18 6892.99,1141.18 U44.3@6901.77,1132.4
NetC94_1: C94.1 R129.2 | length 68
  Top Layer w10: C94.1@7198.58,1295 C94.1@7198.58,1295 R129.2@7198.62,1363
NetC94_2: C94.2 Q1.2 R131.2 | length 268.3
  Top Layer w10: Q1.2@7010.63,1082.6 7012.6,1082.6 7060.65,1130.65 7060.65,1147.18 7140.47,1227 R131.2@7141.38,1227 R131.2@7141.38,1227 C94.2@7141.42,1295
NetC95_2: C95.2 R221.1 U44.4 | length 259.2
  Top Layer w10: v1(6955,1150) 6958.25,1153.25 6958.25,1164.78 7018.42,1224.95 7018.42,1230 C95.2@7021.42,1227
  Bottom Layer w10: v1(6955,1150) 6959.6,1150 6968.42,1141.18 6998.31,1141.18 7007.09,1132.4 7015.87,1141.18 7015.87,1150.04 7037.52,1171.69 7037.52,1181.04 7050.47,1194 R221.1@7051.38,1194 ; U44.4@6983.23,1127.4 U44.4@6992.09,1127.4
NetC97_1: C97.1 R135.1 R140.1 U43.1 | length 454.3
  Top Layer w10: R140.1@7141.38,886 7154.33,873.04 7159.27,873.04 7168.76,863.56 7168.76,863.49 7175.2,857.04 7247.04,857.04 7332.39,942.39 v1(7332.39,977.67) ; C97.1@7291.42,1091 C97.1@7291.42,1091 R135.1@7291.38,1022 7292.28,1022 v1@7332.39,981.89
  Bottom Layer w10: U43.1@7325.83,1028.23 7325.83,1025.2 7325,1024.37 7325,989.66 7332.39,982.27 v1(7332.39,977.67)
NetC98_1: C98.1 R138.2 | length 68.5
  Top Layer w10: R138.2@7141.38,954 R138.2@7141.38,954 C98.1@7141.42,1022 ; C98.1@7154.92,1024.17 C98.1@7155.24,1023.86
NetC98_2: C98.2 R132.2 R133.1 | length 149.2
  Top Layer w10: R132.2@7189.73,1151.02 7197.72,1159 R132.2@7198.62,1159 R133.1@7198.62,1091 R133.1@7198.62,1091 C98.2@7198.58,1022
NetC100_1: C100.1 C172.1 U35.8 | length 246.2
  Top Layer w8: v1(6230,1025) 6258.63,1025 6302.63,981 C100.1@6303.58,981 6296.41,973.83 6296.41,922.27 6315.47,903.21 U35.8@6315.47,889.23
  Bottom Layer w8: C172.1@6183.58,1038 6213.11,1038 6226.11,1025 v1(6230,1025)
NetC101_1: C101.1 R225.1 R230.2 U35.6 | length 265.6
  Top Layer w8: 6354.84,909.23 6358.58,912.97 6358.58,920.12 6373.31,934.86 6373.31,974.11 C101.1@6366.42,981
  Bottom Layer w8: R230.2@6333.62,1106 R225.1@6333.62,1038 6333.62,979.69 v1(6373.31,940) ; v1@6370,939.47 v1@6370.91,939.47
NetC103_1: C103.1 R136.2 R233.1 | length 162.3
  Top Layer w10: C103.1@6126.42,913 6112.56,926.86 6111.61,926.86 6096.73,941.75 6088.25,941.75 v1(6085,945) 6107.04,967.04 6113.42,967.04 R136.2@6126.38,980
  Bottom Layer w10: v1(6085,945) 6088.25,948.25 6103.73,948.25 6125.47,970 R233.1@6126.38,970
NetC105_1: C105.1 U35.3 | length 226.1
  Top Layer w8: U35.3@6404.23,839.84 6460.61,839.84 6480.46,820 6584.44,820 6584.77,820.33 6620.09,820.33 C105.1@6621.42,819
NetC108_1: C108.1 R143.1 | length 71.2
  Top Layer w10: R143.1@6821.38,640 6820,641.38 6820,708.58 C108.1@6821.42,710
NetC109_1: C109.1 C110.1 C111.1 C112.1 L7.2 U35.12 U35.13 U35.14 | length 132.2
  Top Layer w8: 6025,830 6030,825 ; 6295,740 6325,740 6334.89,749.89 6334.89,770.49 U35.14@6335.16,770.77 U35.14@6335.16,757.18
  Top Layer w35: L7.2@5978.43,830 6025,830
NetC109_2: C109.2 C110.2 D18.2 D18.3 L8.1 R245.1
  other v1: 6070,595 5845,615 5875,615 6055,620 6085,620 6070,645
NetC111_2: C111.2 C112.2 D17.2 D17.3 L9.2 R244.1
  other v1: 6370,580 6310,610 6340,610 6370,610 6370,640
NetC113_1: C113.1 U36.4 | length 104.2
  Top Layer w8: C113.1@6678.58,478 6726.58,430 U36.4@6762.91,430
NetC117_1: C117.1 R169.2 R173.2 R174.1 | length 316.3
  Bottom Layer w10: R174.1@7540,6068.62 C117.1@7660,6068.58 ; R169.2@7660,6144.88 C117.1@7660,6068.58 ; R173.2@7780,6068.62 C117.1@7660,6068.58
NetC117_2: C117.2 R45.1 R173.1 U4.1 | length 2178.4
  Top Layer w10: R45.1@6761.38,4566 6720,4607.38 6720,5005 7453.5,5738.5 7713.5,5738.5 7725,5750 7725,5874.61 7712.62,5886.99 7717.01,5891.38 7731.58,5891.38 7741.87,5901.66 7741.87,5998.53 7735,6005.4 v1(7735,6010)
  Bottom Layer w10: C117.2@7660,6011.42 R173.1@7780,6011.38 R173.1@7780,6011.38
NetC118_1: C118.1 R170.2 R175.2 R176.1 | length 316.3
  Bottom Layer w10: R176.1@7180,6068.62 C118.1@7300,6068.58 C118.1@7300,6068.58 ; R170.2@7300,6144.88 C118.1@7300,6068.58 ; R175.2@7420,6068.62 R175.2@7420,6068.62 C118.1@7300,6068.58
NetC118_2: C118.2 R50.1 R175.1 U3.1 | length 1950.8
  Top Layer w10: R50.1@6751.46,4505 6751.46,4507.95 6700,4559.41 6700,5013.28 7359.39,5672.67 7359.39,5873.82 7350.61,5882.6 U3.1@7348.23,5882.6 7357.01,5891.38 7371.58,5891.38 7381.87,5901.66 7381.87,5998.53 7375,6005.4 v1(7375,6010)
  Bottom Layer w10: C118.2@7300,6011.42 C118.2@7300,6011.42 R175.1@7420,6011.38
NetC119_1: C119.1 R171.2 R177.2 R178.1 | length 316.4
  Bottom Layer w10: R178.1@6820,6068.62 R178.1@6820,6068.62 C119.1@6940,6068.58 C119.1@6940,6068.58 ; R171.2@6940,6144.88 C119.1@6940,6068.58 ; R177.2@7060,6068.62 C119.1@6940,6068.58 C119.1@6940,6068.58
NetC119_2: C119.2 R55.1 R177.1 U2.1 | length 1959
  Top Layer w10: R55.1@6761.38,4432 6756.23,4437.15 6707.85,4437.15 6680,4465 6680,5021.57 7030,5371.57 7030,5849.09 7005.87,5873.23 7005.87,5873.82 6992.95,5886.73 6992.36,5886.73 6996.5,5890.87 7024.13,5890.87 7029.99,5896.72 7029.99,5967.61 7016.1,5981.5 7016.1,6008.9 v1(7015,6010)
  Bottom Layer w10: C119.2@6940,6011.42 R177.1@7060,6011.38 R177.1@7060,6011.38
NetC120_1: C120.1 R172.2 R179.1 R180.1 | length 316.3
  Bottom Layer w10: R180.1@6460,6068.62 C120.1@6580,6068.58 C120.1@6580,6068.58 ; R172.2@6580,6144.88 C120.1@6580,6068.58 ; R179.1@6700,6068.62 R179.1@6700,6068.62 C120.1@6580,6068.58
NetC120_2: C120.2 R57.1 R179.2 U1.1 | length 1857.1
  Top Layer w10: v1(6653.58,6011.42) 6653.58,6006.82 6661.87,5998.53 6661.87,5901.66 6651.58,5891.38 6637.01,5891.38 U1.1@6628.23,5882.6 6637.09,5882.6 6645.87,5873.82 6645.87,5864.96 6660,5850.83 6660,4452.95 R57.1@6755,4357.95
  Bottom Layer w10: C120.2@6580,6011.42 v1(6653.58,6011.42) R179.2@6700,6011.38 R179.2@6700,6011.38
NetC129_1: C129.1 R184.2 U38.3 | length 151.5
  Bottom Layer w10: U38.3@7118.23,4472.6 U38.3@7119.8,4472.6 ; C129.1@7128.58,4411 7128.58,4463.82 U38.3@7119.8,4472.6 ; R184.2@7201.38,4480 7193.98,4472.6 U38.3@7119.8,4472.6
NetC130_1: C130.1 R186.1 U38.4 | length 173.9
  Bottom Layer w10: R186.1@6941.38,4343 C130.1@6941.42,4411 C130.1@6941.42,4411 6942.37,4411 6995.19,4463.82 7012.99,4463.82 U38.4@7021.77,4472.6
NetC130_2: C130.2 R186.2 R189.1 U38.1 | length 605.8
  Bottom Layer w10: R189.1@6761.38,4139 6762.28,4139 6775.24,4151.96 6775.24,4175.24 6865,4265 6919.72,4265 6997.72,4343 R186.2@6998.62,4343 C130.2@6998.58,4411 C130.2@6998.58,4411 6999.53,4411 7028.09,4439.56 7040.71,4439.56 7065.87,4464.73 7065.87,4509.62 7094.88,4538.62 7109.45,4538.62 U38.1@7118.23,4547.4
NetC135_1: C135.1 R188.2 U40.3 | length 151
  Bottom Layer w10: U40.3@7118.23,4200.6 U40.3@7119.8,4200.6 ; C135.1@7128.58,4139 7128.58,4191.82 U40.3@7119.8,4200.6 ; R188.2@7201.38,4207 7194.98,4200.6 U40.3@7119.8,4200.6
NetC136_1: C136.1 R191.1 U40.4 | length 174.9
  Bottom Layer w10: R191.1@6941.38,4070 C136.1@6941.42,4139 C136.1@6941.42,4139 6942.37,4139 6995.19,4191.82 7012.99,4191.82 U40.4@7021.77,4200.6
NetC136_2: C136.2 R191.2 R192.1 U40.1 | length 532.7
  Bottom Layer w10: R192.1@6761.38,4070 6762.28,4070 6791.24,4041.04 6968.76,4041.04 6997.72,4070 R191.2@6998.62,4070 C136.2@6998.58,4139 C136.2@6998.58,4139 6999.53,4139 7028.09,4167.56 7040.71,4167.56 7065.87,4192.73 7065.87,4237.62 7094.88,4266.62 7109.45,4266.62 U40.1@7118.23,4275.4
NetC141_1: C141.1 R194.2 U41.3 | length 152.6
  Bottom Layer w10: C141.1@7128.58,3868 7128.58,3920.82 7119.8,3929.6 7118.23,3929.6 7124.63,3936 R194.2@7201.38,3936
NetC142_1: C142.1 R196.1 U41.4 | length 177.7
  Bottom Layer w10: R196.1@6941.38,3800 6946.04,3804.67 6946.04,3863.38 C142.1@6941.42,3868 6942.37,3868 6980.52,3906.15 6989.46,3906.15 7012.91,3929.6 U41.4@7021.77,3929.6
NetC142_2: C142.2 R64.1 R196.2 U41.1 | length 767.6
  Top Layer w10: v1(6715,4040) 6759.38,4040 R64.1@6761.38,4042
  Bottom Layer w10: v1(6715,4040) 6818.11,3936.89 6818.11,3870.9 6919.01,3770 6967.72,3770 6997.72,3800 R196.2@6998.62,3800 C142.2@6998.58,3868 C142.2@6998.58,3868 6999.53,3868 7028.09,3896.56 7045.75,3896.56 7047.05,3897.86 7047.86,3897.86 7065.87,3915.87 7065.87,3966.62 7094.88,3995.62 7109.45,3995.62 U41.1@7118.23,4004.4
NetC169_2: C169.2 R222.2 R235.2 U45.3 | length 581.6
  Top Layer w10: v1(7675,990) 7675,1019.69 7735,1079.69 v1(7735,1145)
  Bottom Layer w10: U45.3@7437.4,938.23 7437.4,929.37 7446.82,919.96 7488.42,919.96 R235.2@7501.38,907 7502.28,907 7560.44,965.16 7660.16,965.16 7660.16,970.56 7675,985.4 v1(7675,990) ; v1(7735,1145) 7770.38,1145 R222.2@7771.38,1146 C169.2@7771.42,1215 C169.2@7771.42,1215
NetC170_1: C170.1 R218.2 R221.2 R224.1 | length 285.6
  Bottom Layer w10: C170.1@6988.58,1194 R218.2@6988.62,1263 7038.76,1262.96 7107.72,1194 R221.2@7108.62,1194 R224.1@7108.62,1126
NetC171_1: C171.1 R128.1 R220.1 U43.5 | length 472.3
  Top Layer w10: R128.1@7198.62,1432 7233,1432 7270,1395 7270,1343.99 7270.39,1343.6 7270.39,1281.7 7270,1281.31 v1(7270,1243.34)
  Bottom Layer w10: v1(7270,1243.34) 7228.58,1201.92 C171.1@7228.58,1126 7230.38,1127.8 7323.04,1127.8 U43.5@7325.83,1130.59
NetC172_2: C172.2 R226.2 | length 68
  Bottom Layer w10: C172.2@6126.42,1038 C172.2@6126.42,1038 R226.2@6126.38,1106
NetC173_1: C173.1 R229.2 R232.1 U43.2 U43.4 | length 712.5
  Bottom Layer w10: U43.2@7325.83,1053.82 7285.39,1053.82 7260.61,1029.04 7211.42,1029.04 7160.61,978.24 7160.61,961.33 7114.28,915 7085,915 7070.52,929.48 7070.52,956.77 7087.21,973.46 7091.18,973.46 7107.72,990 R232.1@7108.62,990 R229.2@7108.62,1058 7109.53,1058 7139.51,1087.98 7262.98,1087.98 7280,1105 U43.4@7325.83,1105
NetC175_1: C175.1 U35.10 | length 127.1
  Top Layer w8: 6255.76,839.84 U35.10@6285.77,839.84
  Top Layer w10: v1(6223.84,871.76) 6255.76,839.84
  Bottom Layer w10: C175.1@6183.58,900 6184.53,900 6209.51,875.02 6220.59,875.02 v1(6223.84,871.76)
NetC178_1: C178.1 R237.2 R238.2 U45.4 | length 317.6
  Bottom Layer w10: R237.2@7222,836.38 7289.09,836.38 7320.47,805 7400.63,805 7419.76,824.13 7428.62,824.13 7437.4,832.91 U45.4@7437.4,841.77 7498.61,841.77 R238.2@7501.38,839 R238.2@7498.8,836.42
NetC178_2: C178.2 R58.1 R237.1 U45.1 | length 3729.1
  Top Layer w10: R58.1@7238.62,4236 7251.58,4223.04 7257.26,4223.04 7295.38,4184.92 7333.5,4146.81 7333.5,3985.91 7329.39,3981.81 7329.39,3764.54 7328.71,3763.86 7328.71,3676.64 7378.86,3626.5 7378.86,3075 7340,3036.14 7340,2678.28 7445,2573.28 7445,1460 7318.5,1333.5 7318.5,1219.91 7290.09,1191.5 7275.18,1191.5 7250,1166.32 7250,977.14 v1(7288.42,938.72)
  Bottom Layer w10: R237.1@7222,893.62 C178.2@7290,893.58 C178.2@7290,893.58 7290,894.53 C178.2@7295.25,899.78 ; v1(7288.42,938.72) 7288.42,906.62 C178.2@7295.25,899.78 ; U45.1@7362.6,938.23 7333.7,938.23 C178.2@7295.25,899.78
NetC181_1: C181.1 R241.2 R242.2 U46.4 | length 440.5
  Bottom Layer w10: R241.2@7222,716.38 C181.1@7290,716.42 C181.1@7290,716.42 7300,706.42 7300,650 7355,595 7415.31,595 7437.4,617.1 U46.4@7437.4,673.54 7471.02,673.54 7500.47,703 R242.2@7501.38,703
NetC181_2: C181.2 R63.1 R241.1 U46.1 | length 3740.3
  Top Layer w10: R63.1@7238.62,4100 7239.53,4100 7309.39,4030.14 7309.39,3772.82 7308.71,3772.15 7308.71,3668.36 7358.86,3618.21 7358.86,3083.28 7320,3044.42 7320,2670 7420,2570 7420,1480 7298.5,1358.5 7298.5,1228.19 7281.81,1211.5 7266.9,1211.5 7230,1174.6 7230,957.63 7249.75,937.88 v1(7249.75,937.08)
  Bottom Layer w10: v1(7249.75,937.08) 7227.08,937.08 7225,935 7211.01,935 7180,903.99 7180,816.53 7222,774.53 R241.1@7222,773.62 R241.1@7222,773.62 C181.2@7290,773.58 7293.58,770 U46.1@7362.6,770
NetC185_2: C185.2 R240.2 R243.2 U46.3 | length 930.9
  Top Layer w10: v1(7395,623.5) 7395,598.78 7449.52,544.26 7500.79,492.99 7531.81,492.99 7533.81,495 7588.59,495 7672.09,578.5 7716.81,578.5 7730.31,565 v1(7870,565)
  Bottom Layer w10: v1(7395,623.5) 7395,696.67 7430.69,732.36 7430.69,763.29 U46.3@7437.4,770 7500.38,770 R240.2@7501.38,771 ; R243.2@7828.62,652 R243.2@7828.62,652 C185.2@7828.58,583 7842.44,569.14 7861.26,569.14 7865.4,565 v1(7870,565)
NetC189_1: C189.1 R244.2
NetC198_1: C198.1 R245.2
NetD1_2: D1.2 R204.1 | length 565.9
  Top Layer w10: D1.2@7461.34,3012 7461.34,3221.34 7610,3370 v1(7700,3370)
  Bottom Layer w10: R204.1@7653.62,3358 7686.29,3358 7698.29,3370 v1(7700,3370) v1@7705,3370
NetD2_2: D2.2 R206.1 | length 588.4
  Top Layer w10: D2.2@7461.34,2930 7500,2968.66 7500,3228.08 7571.92,3300 v1(7700,3300)
  Bottom Layer w10: R206.1@7653.62,3290 7686.29,3290 7692.59,3296.3 7693.7,3296.3 v1@7695,3295
NetD3_2: D3.2 R208.1 | length 584
  Top Layer w10: D3.2@7461.34,2848 7525,2911.66 7525,3150 7610,3235 7676.81,3235 7686.11,3244.29 v1(7690.71,3244.29)
  Bottom Layer w10: R208.1@7653.62,3222 7666.58,3234.96 7676.77,3234.96 7686.81,3245 v1@7695,3245
NetD4_2: D4.2 R215.2 | length 143.9
  Top Layer w10: D4.2@6685,1425 6691.34,1425 6721.75,1455.41 6721.75,1476.75 v1(6725,1480)
  Bottom Layer w10: R215.2@6704.1,1420 6725,1440.9 v1(6725,1480)
NetD5_2: D5.2 R216.2 | length 224.6
  Top Layer w10: v1@6538.25,1333.25 v1(6535,1330) 6564.62,1300.38 6651.72,1300.38 D5.2@6686.34,1335
  Bottom Layer w10: v1(6535,1330) 6570,1330 R216.2@6575,1325
NetD6_2: D6.2 R223.1 R227.1 | length 283.5
  Top Layer w25: D6.2@6690,1255 6690,1246.34 6726.34,1210 6730,1210 6730,1125.54 6715,1110.54 v1(6715,1110)
  Bottom Layer w25: R227.1@6673.62,1087 6679.08,1092.46 6697.46,1092.46 v1(6715,1110) 6714.62,1110.38 6714.62,1114.91 6674.53,1155 R223.1@6673.62,1155
NetD7_2: D7.2 R231.2 R234.2 | length 297.7
  Top Layer w25: D7.2@6686.34,1170 6679,1162.66 6679,1051.12 6715,1015.12 v1(6715,1015)
  Bottom Layer w25: R234.2@6673.62,951 6679.08,956.46 6679.98,956.46 6715,991.47 v1(6715,1015) 6712.12,1017.88 6674.74,1017.88 R231.2@6673.62,1019
NetD11_2: D11.2 R74.2 | length 149.9
  Top Layer w25: v1(6170,3630) 6170.38,3629.62 6212.95,3629.62 6230,3612.57 R74.2@6230,3610
  Bottom Layer w25: D11.2@6145.67,3700 6162.7,3682.97 6162.7,3637.84 6170,3630.54 v1(6170,3630)
NetD12_2: D12.2 R73.2 | length 315.8
  Top Layer w25: R73.2@890,3610 v1(940,3610)
  Bottom Layer w25: D12.2@712.6,3700 712.6,3698.03 800.63,3610 v1(940,3610)
NetD13_2: D13.2 R108.2 | length 348.9
  Top Layer w25: v1(6200,2300) 6200.38,2300.38 6270.36,2300.38 6285,2315.03 6285,2431.28 6270.36,2445.92 6245.26,2445.92 6240,2451.18 R108.2@6240,2485
  Bottom Layer w25: D13.2@6145.67,2300 v1(6200,2300)
NetD14_2: D14.2 R110.2 | length 138.7
  Top Layer w25: v1(710,2355) 710.54,2355 721.46,2365.92 754.74,2365.92 765,2376.18 R110.2@765,2395
  Bottom Layer w25: v1(710,2355) 710.38,2354.62 710.38,2302.22 D14.2@712.6,2300
NetD15_2: D15.2 J11.2 Q3.4 | length 140
  Bottom Layer w50: Q3.4@7615,2315.24 7755,2315.24
NetD16_2: D16.2 J15.2 Q4.4 | length 140.2
  Bottom Layer w8: 7755,1700 7755,1700.24
  Bottom Layer w50: Q4.4@7615,1700.24 7755,1700.24
NetHS1_3: HS1.3 R125.2 R126.2
NetJ8_5: J8.5 R65.1 | length 1094.7
  Top Layer w10: R65.1@7238.62,3964 7239.53,3964 7289.39,3914.14 7289.39,3781.11 7275,3766.72 v1(7275,3465)
  Bottom Layer w10: v1(7275,3465) 7279.6,3465 7294.6,3450 J8.5@7837,3450
NetJ8_6: J8.6 R66.1 | length 1210.6
  Top Layer w10: R66.1@7238.62,3896 7238.62,3863.72 7244.48,3857.86 7262.95,3857.86 7269.39,3851.42 7269.39,3789.39 7246.5,3766.5 7246.5,3448.41 v1(7274.98,3419.94)
  Bottom Layer w10: v1(7274.98,3419.94) 7278.47,3419.94 7296.88,3401.54 7888.54,3401.54 J8.6@7937,3450
NetJ8_7: J8.7 R210.1 | length 663
  Bottom Layer w10: R210.1@7258.62,3200 7259.53,3200 7284.53,3175 7665,3175 7837,3347 J8.7@7837,3350
NetJ8_8: J8.8 R211.1 | length 768.3
  Bottom Layer w10: R211.1@7258.62,3133 7271.58,3145.96 7393.25,3145.96 7402.29,3155 7673.43,3155 7816.9,3298.46 7885.46,3298.46 J8.8@7937,3350
NetJ8_9: J8.9 R212.1 | length 654.6
  Bottom Layer w10: R212.1@7258.62,3066 7341.58,3066 7410.58,3135 7681.72,3135 7788.54,3241.82 7828.82,3241.82 J8.9@7837,3250
NetJ8_10: J8.10 R213.1 | length 782.8
  Bottom Layer w10: R213.1@7258.62,2998 7301.86,2998 7418.86,3115 7690,3115 7775,3200 7887,3200 J8.10@7937,3250
NetQ1_3: Q1.3 R132.1 | length 88.5
  Top Layer w10: Q1.3@7091.34,1120 Q1.3@7089.37,1120 7100.12,1130.75 7112.22,1130.75 7140.47,1159 R132.1@7141.38,1159 R132.1@7128.42,1146.04
NetQ3_1: Q3.1 R214.2 | length 141.3
  Bottom Layer w10: R214.2@7670,1899.76 7670,1907.69 7705,1942.69 7705,2026.38 Q3.1@7705.16,2026.54
NetQ4_1: Q4.1 R217.2 | length 149.5
  Bottom Layer w10: R217.2@7670,1280 7670,1281.34 7693.66,1305 7699.14,1305 7705,1310.86 7705,1411.61 Q4.1@7705.16,1411.77
NetQ5_4: Q5.4 Q6.4 R145.2 U36.10 | length 503.8
  Top Layer w10: v1(6756.95,788.05) 6780,765 6780,586.36 ; v1(6785,572) 6819.38,572 R145.2@6821.38,570 6821.75,570 6834.7,557.04 6834.7,545.3 6856.34,523.66 6883.41,523.66 6917.7,489.37 U36.10@6931.5,489.37
  Bottom Layer w10: v1(6756.95,788.05) 6758.47,786.53 6810.32,786.53 Q5.4@6811.3,787.5 ; v1(6785,572) 6785,567.4 6790.55,561.85 6790.55,542.01 6797.56,535 Q6.4@6804.88,535
NetR14_2: R14.2 R18.1 | length 79.8
  Top Layer w10: R18.1@6940,7015.12 R14.2@6940,7094.88
NetR15_2: R15.2 R19.1 | length 79.8
  Top Layer w10: R19.1@7300,7015.12 R15.2@7300,7094.88
NetR16_2: R16.2 R20.1 | length 79.8
  Top Layer w10: R20.1@7660,7015.12 R16.2@7660,7094.88
NetR18_2: R18.2 R22.1 | length 79.8
  Top Layer w10: R22.1@6940,6825.12 R18.2@6940,6904.88
NetR19_2: R19.2 R23.1 | length 79.8
  Top Layer w10: R23.1@7300,6825.12 R19.2@7300,6904.88
NetR20_2: R20.2 R24.1 | length 79.8
  Top Layer w10: R24.1@7660,6825.12 R20.2@7660,6904.88
NetR22_2: R22.2 R26.1 | length 79.8
  Top Layer w10: R26.1@6940,6635.12 R22.2@6940,6714.88
NetR23_2: R23.2 R27.1 | length 79.8
  Top Layer w10: R27.1@7300,6635.12 R23.2@7300,6714.88
NetR24_2: R24.2 R28.1 | length 79.8
  Top Layer w10: R28.1@7660,6635.12 R24.2@7660,6714.88
NetR26_2: R26.2 R30.1 | length 79.8
  Top Layer w10: R30.1@6940,6445.12 R26.2@6940,6524.88
NetR27_2: R27.2 R31.1 | length 79.8
  Top Layer w10: R31.1@7300,6445.12 R27.2@7300,6524.88
NetR28_2: R28.2 R32.1 | length 79.8
  Top Layer w10: R32.1@7660,6445.12 R28.2@7660,6524.88
NetR30_2: R30.2 R34.1 | length 79.8
  Top Layer w10: R34.1@6940,6255.12 R30.2@6940,6334.88
NetR31_2: R31.2 R35.1 | length 79.8
  Top Layer w10: R35.1@7300,6255.12 R31.2@7300,6334.88
NetR32_2: R32.2 R36.1 | length 79.8
  Top Layer w10: R36.1@7660,6255.12 R32.2@7660,6334.88
NetR37_2: R37.2 U1.3 | length 79.1
  Top Layer w10: R37.2@6580,6011.38 6580,6010.47 6610.59,5979.88 6610.59,5966.18 6619.37,5957.4 U1.3@6628.23,5957.4
NetR39_2: R39.2 U2.3 | length 84.1
  Top Layer w10: R39.2@6940,6011.38 6940,6010.47 6970.59,5979.88 6970.59,5961.18 6979.37,5952.4 U2.3@6988.23,5952.4
NetR41_2: R41.2 U3.3 | length 79.1
  Top Layer w10: R41.2@7300,6011.38 7300,6010.47 7330.59,5979.88 7330.59,5966.18 7339.37,5957.4 U3.3@7348.23,5957.4
NetR43_2: R43.2 U4.3 | length 79.1
  Top Layer w10: R43.2@7660,6011.38 7660,6010.47 7690.59,5979.88 7690.59,5966.18 7699.37,5957.4 U4.3@7708.23,5957.4
NetR73_1: R73.1 R79.2 | length 81.7
  Top Layer w25: R79.2@770.9,3530 770.9,3605.9 R73.1@775,3610
NetR74_1: R74.1 R80.2 | length 158.9
  Top Layer w25: R74.1@6110.9,3610 6110.9,3602.08 6127.05,3585.92 6146.37,3585.92 6178.22,3554.08 6212.95,3554.08 6225,3542.03 R80.2@6225,3530
NetR84_1: R84.1 U18.7 | length 154.9
  Top Layer w10: U18.7@6638.06,3185 6680.64,3185 6686.5,3190.86 6686.5,3196.81 6714.03,3224.33 6752.28,3224.33 6765,3237.05 R84.1@6765,3240
NetR85_1: R85.1 U18.6 | length 152.8
  Top Layer w10: U18.6@6638.06,3135 6720,3135 6748.67,3163.67 6748.67,3176.04 6752.63,3180 R85.1@6765,3180
NetR86_1: R86.1 U21.7 | length 219.8
  Top Layer w10: U21.7@6623.06,2975 6654.3,2975 6702.21,3022.91 6702.21,3053.89 6747.65,3099.33 6752.28,3099.33 6765,3112.05 R86.1@6765,3115
NetR90_1: R90.1 U21.6 | length 206.2
  Top Layer w10: U21.6@6623.06,2925 6654.3,2925 6673,2943.7 6673,2961.94 6703.48,2992.42 6703.48,2992.62 6762.91,3052.05 R90.1@6762.91,3055
NetR96_1: R96.1 U23.7 | length 333.6
  Top Layer w10: U23.7@6621.11,2765 6675,2765 6750,2840 6750,2880 6731.22,2898.78 6731.22,2956.81 6747.52,2973.11 6747.52,2975.04 R96.1@6764.52,2992.05
NetR100_1: R100.1 U23.6 | length 290.1
  Top Layer w10: U23.6@6621.11,2715 6652.35,2715 6682.35,2745 6683.28,2745 6770,2831.72 6770,2912.38 R100.1@6761.38,2921
NetR107_2: R107.2 R110.1 | length 163.1
  Top Layer w25: R107.2@770.9,2470 770.9,2462.08 787.05,2445.92 806.37,2445.92 838.22,2414.08 872.95,2414.08 895,2392.03 R110.1@895,2390
NetR108_1: R108.1 R111.2 | length 159.8
  Top Layer w25: R108.1@6110.9,2470 6110.9,2462.08 6127.05,2445.92 6146.37,2445.92 6178.22,2414.08 6215.92,2414.08 R111.2@6235,2395
NetR128_2: R128.2 R129.1 | length 69
  Top Layer w10: R129.1@7141.38,1363 R128.2@7141.38,1432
